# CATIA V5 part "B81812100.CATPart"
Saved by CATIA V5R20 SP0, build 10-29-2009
Part number: B81812100
Revision: 3
Definition: design
Nomenclature: B81812100
Source: made
Description: NOT SPECIFIED
Bounding box of the stored display mesh (mm): x -8 to 8, y -8 to 8, z 0 to 100
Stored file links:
  C:\Users\Raffaele\Desktop\3D X SITO CF\BOLEX\6-PILLAR REF 818\B81812100.CATPart
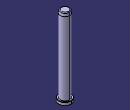
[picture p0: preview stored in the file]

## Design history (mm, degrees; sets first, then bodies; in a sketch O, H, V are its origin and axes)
Body1 "MANIFOLD_SOLID_BREP #370" (main body)
  Solid1: solid without history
